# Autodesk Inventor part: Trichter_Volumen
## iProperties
Created: 2010-10
Part Number: Trichter_Volumen
Document SubType Name: Modeling
Designer: M.Grouls
Mass: 4.24224e+06 g
Surface Area: 44729.6 cm^2
Volume: 541101 cm^3
Density: 7.84 g/cm^3
Author: M.Grouls
